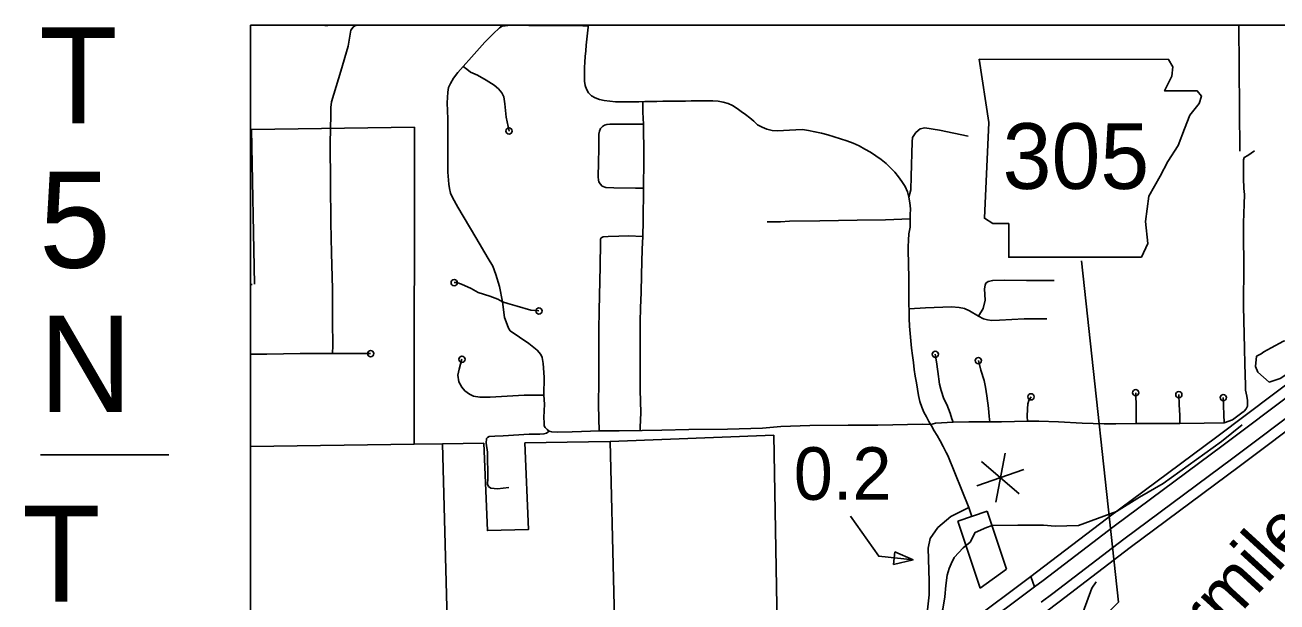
# Model space of a CAD drawing. Extents: x 1367863 to 1368197, y 380048 to 380261.
# Drawn here: x 1367952.41 to 1367991.45, y 380159.47 to 380177.46 of the extents above; entities that cross this region are included whole.
import ezdxf

# ---------------------------------------------------------------- set-up
doc = ezdxf.new("R2010")
doc.units = 0
for name, color, linetype in [('Level 10', 7, 'Continuous'), ('Level 15', 7, 'Continuous'), ('Level 21', 7, 'Continuous'), ('Level 31', 7, 'Continuous'), ('Level 33', 7, 'Continuous'), ('Level 34', 7, 'Continuous'), ('Level 35', 7, 'Continuous'), ('Level 45', 7, 'Continuous'), ('Level 48', 7, 'Continuous'), ('Level 5', 7, 'Continuous'), ('Level 6', 7, 'Continuous'), ('R_Border', 7, 'Continuous'), ('R_Draft', 7, 'Continuous'), ('R_No Plot', 7, 'Continuous')]:
    doc.layers.add(name, color=color, linetype=linetype)

msp = doc.modelspace()

# ---------------------------------------------------------------- linework, layer by layer
at = {"layer": 'Level 10'}
msp.add_line((1367982.191, 380159.898), (1367983.016, 380160.493), dxfattribs=at)
for points in [[(1367982.415, 380162.299), (1367981.495, 380161.993)], [(1367983.016, 380160.493), (1367982.415, 380162.299)], [(1367981.495, 380161.993), (1367982.191, 380159.898)]]:
    msp.add_lwpolyline(points, dxfattribs=at)
at = {"layer": 'Level 15'}
for p, q in [((1367981.823, 380158.812), (1367983.775, 380160.267)), ((1367983.888, 380159.94), (1367981.956, 380158.5))]:
    msp.add_line(p, q, dxfattribs=at)
for points in [[(1367983.775, 380160.267), (1367983.952, 380160.4), (1367986.169, 380162.096), (1367989.568, 380164.62), (1367994.115, 380168.041), (1367995.437, 380169.06), (1367995.925, 380169.499), (1367996.299, 380169.836), (1367997.817, 380171.432), (1367998.192, 380171.917), (1367999.213, 380173.375), (1368001.597, 380177.46)], [(1368001.979, 380177.46), (1367999.491, 380173.197), (1367998.457, 380171.722), (1367998.068, 380171.217), (1367996.529, 380169.599), (1367996.145, 380169.254), (1367995.648, 380168.807), (1367994.315, 380167.778), (1367989.766, 380164.356), (1367986.367, 380161.832), (1367984.151, 380160.136), (1367983.888, 380159.94)], [(1367984.089, 380159.461), (1367984.455, 380159.734), (1367986.671, 380161.43), (1367990.068, 380163.952), (1367994.62, 380167.377), (1367995.971, 380168.419), (1367996.483, 380168.878), (1367996.881, 380169.237), (1367998.451, 380170.888), (1367998.864, 380171.423), (1367999.916, 380172.924), (1368002.563, 380177.46)], [(1368002.944, 380177.46), (1368002.871, 380177.333), (1368000.194, 380172.746), (1367999.13, 380171.227), (1367998.702, 380170.673), (1367997.112, 380169.001), (1367996.703, 380168.633), (1367996.182, 380168.165), (1367994.82, 380167.114), (1367990.266, 380163.688), (1367986.87, 380161.166), (1367984.654, 380159.47), (1367984.225, 380159.15)], [(1367983.775, 380160.267), (1367983.888, 380159.94)], [(1367983.888, 380159.94), (1367983.775, 380160.267)]]:
    msp.add_lwpolyline(points, dxfattribs=at)
at = {"layer": 'Level 21'}
msp.add_lwpolyline([(1367982.162, 380176.391), (1367982.457, 380174.421), (1367982.326, 380171.433), (1367982.589, 380171.269), (1367983.081, 380171.269), (1367983.081, 380170.219), (1367987.218, 380170.219), (1367987.415, 380170.645), (1367987.349, 380171.335), (1367987.447, 380172.123), (1367987.808, 380172.747), (1367988.038, 380173.206), (1367988.367, 380173.699), (1367988.564, 380174.224), (1367988.728, 380174.651), (1367989.023, 380175.012), (1367989.089, 380175.242), (1367988.958, 380175.406), (1367987.94, 380175.406), (1367988.17, 380175.865), (1367988.202, 380176.161), (1367988.066, 380176.388)], close=True, dxfattribs=at)
msp.add_lwpolyline([(1367985.353, 380170.106), (1367986.507, 380159.464), (1367984.684, 380157.641)], dxfattribs=at)
at = {"layer": 'Level 31'}
for points in [[(1367961.935, 380174.233), (1367961.921, 380173.766), (1367961.941, 380172.529), (1367961.947, 380171.302), (1367961.968, 380170.349), (1367961.994, 380169.231), (1367962.001, 380168.218), (1367962.014, 380167.467), (1367962.001, 380167.212)], [(1367963.188, 380167.212), (1367962.558, 380167.219), (1367962.001, 380167.212), (1367960.995, 380167.212), (1367959.949, 380167.199), (1367959.444, 380167.199)]]:
    msp.add_lwpolyline(points, dxfattribs=at)
msp.add_circle((1367963.188, 380167.212), 0.097, dxfattribs=at)
at = {"layer": 'Level 33'}
for points in [[(1367962.114, 380177.46), (1367961.854, 380177.449), (1367961.76, 380177.442)], [(1367962.787, 380177.46), (1367962.698, 380177.435), (1367962.645, 380177.395), (1367962.571, 380177.301), (1367962.484, 380176.804), (1367962.256, 380176.026), (1367961.968, 380175.06), (1367961.947, 380174.886), (1367961.947, 380174.638), (1367961.935, 380174.233)], [(1367962.698, 380177.435), (1367962.564, 380177.456), (1367962.499, 380177.46)], [(1367966.075, 380176.167), (1367966.33, 380176.462), (1367966.752, 380176.925), (1367967.007, 380177.187), (1367967.208, 380177.375), (1367967.289, 380177.428)], [(1367967.289, 380177.428), (1367967.203, 380177.46)], [(1367967.289, 380177.428), (1367967.561, 380177.46)], [(1367967.795, 380177.46), (1367968.12, 380177.442), (1367968.925, 380177.448), (1367969.803, 380177.435), (1367969.973, 380177.439)], [(1367980.111, 380166.932), (1367980.082, 380167.153), (1367980.055, 380167.38), (1367980.029, 380167.607), (1367980.005, 380167.837), (1367979.987, 380168.069), (1367979.98, 380168.303), (1367979.973, 380168.537), (1367979.972, 380168.769), (1367979.971, 380169.001), (1367979.967, 380169.229), (1367979.966, 380169.456), (1367979.965, 380169.68), (1367979.962, 380169.902), (1367979.957, 380170.119), (1367979.951, 380170.332), (1367979.948, 380170.542), (1367979.954, 380170.748), (1367979.972, 380170.952), (1367980.007, 380171.152), (1367980.005, 380171.353), (1367980.009, 380171.546), (1367980.016, 380171.73), (1367980, 380171.91), (1367979.971, 380172.087), (1367979.928, 380172.255), (1367979.849, 380172.42), (1367979.752, 380172.576), (1367979.647, 380172.728), (1367979.527, 380172.87), (1367979.394, 380173.004), (1367979.257, 380173.144), (1367979.104, 380173.268), (1367978.941, 380173.382), (1367978.772, 380173.491), (1367978.597, 380173.593), (1367978.416, 380173.689), (1367978.23, 380173.773), (1367978.037, 380173.847), (1367977.84, 380173.912), (1367977.641, 380173.973), (1367977.442, 380174.033), (1367977.242, 380174.086), (1367977.042, 380174.132), (1367976.842, 380174.169), (1367976.651, 380174.199), (1367976.445, 380174.188), (1367976.25, 380174.181), (1367976.061, 380174.169), (1367975.877, 380174.163), (1367975.704, 380174.176), (1367975.544, 380174.214), (1367975.393, 380174.273), (1367975.25, 380174.345), (1367975.134, 380174.46), (1367975.007, 380174.562), (1367974.878, 380174.666), (1367974.745, 380174.766), (1367974.612, 380174.862), (1367974.475, 380174.948), (1367974.33, 380175.015), (1367974.178, 380175.058), (1367974.021, 380175.084), (1367973.858, 380175.091), (1367973.695, 380175.097), (1367973.527, 380175.096), (1367973.356, 380175.093), (1367973.183, 380175.091), (1367973.008, 380175.09), (1367972.833, 380175.088), (1367972.656, 380175.085), (1367972.477, 380175.083), (1367972.296, 380175.081), (1367972.112, 380175.08), (1367971.927, 380175.078), (1367971.741, 380175.075), (1367971.554, 380175.069), (1367971.369, 380175.066), (1367971.184, 380175.062), (1367971.001, 380175.063), (1367970.818, 380175.07), (1367970.642, 380175.087), (1367970.472, 380175.109), (1367970.319, 380175.142), (1367970.187, 380175.189), (1367970.074, 380175.257), (1367969.982, 380175.348), (1367969.916, 380175.457), (1367969.877, 380175.577), (1367969.858, 380175.705), (1367969.851, 380175.841), (1367969.852, 380175.986), (1367969.858, 380176.14), (1367969.863, 380176.303), (1367969.881, 380176.474), (1367969.894, 380176.651), (1367969.909, 380176.833), (1367969.926, 380177.017), (1367969.945, 380177.204), (1367969.967, 380177.389)], [(1367969.967, 380177.389), (1367969.975, 380177.46)], [(1367966.853, 380170.181), (1367966.47, 380170.83), (1367965.907, 380171.782), (1367965.74, 380172.084), (1367965.679, 380172.219), (1367965.646, 380172.366), (1367965.626, 380172.5), (1367965.592, 380172.876), (1367965.599, 380173.547), (1367965.592, 380174.533), (1367965.579, 380175.033), (1367965.599, 380175.369), (1367965.612, 380175.516), (1367965.679, 380175.637), (1367965.773, 380175.798), (1367965.907, 380175.979), (1367966.075, 380176.167)], [(1367967.503, 380174.155), (1367967.416, 380174.591), (1367967.376, 380175.007), (1367967.342, 380175.221), (1367967.275, 380175.349), (1367967.175, 380175.469), (1367967.04, 380175.584), (1367966.792, 380175.745), (1367966.517, 380175.892), (1367966.303, 380175.986), (1367966.189, 380176.08), (1367966.075, 380176.167)], [(1367971.672, 380170.862), (1367971.681, 380171.357), (1367971.698, 380172.376), (1367971.704, 380173.25), (1367971.701, 380173.659), (1367971.698, 380174.112), (1367971.694, 380174.364), (1367971.674, 380174.745), (1367971.671, 380175.073)], [(1367971.694, 380174.364), (1367971.279, 380174.366), (1367970.648, 380174.373), (1367970.548, 380174.359), (1367970.477, 380174.339), (1367970.417, 380174.299), (1367970.35, 380174.235), (1367970.32, 380174.155), (1367970.303, 380174.057), (1367970.303, 380173.608), (1367970.296, 380173.168), (1367970.279, 380172.727), (1367970.289, 380172.62), (1367970.299, 380172.57), (1367970.34, 380172.506), (1367970.41, 380172.432), (1367970.524, 380172.392), (1367970.772, 380172.382), (1367971.446, 380172.372), (1367971.698, 380172.376)], [(1367980.006, 380171.411), (1367979.241, 380171.386), (1367978.361, 380171.378), (1367977.196, 380171.352), (1367976.248, 380171.344), (1367975.963, 380171.319), (1367975.553, 380171.319)], [(1367970.314, 380164.799), (1367970.297, 380165.605), (1367970.307, 380166.373), (1367970.3, 380167.313), (1367970.3, 380167.957), (1367970.314, 380168.561), (1367970.347, 380169.944), (1367970.357, 380170.678), (1367970.354, 380170.781), (1367970.378, 380170.821), (1367970.441, 380170.852), (1367970.596, 380170.862), (1367970.931, 380170.875), (1367971.226, 380170.885), (1367971.672, 380170.862)], [(1367971.672, 380170.862), (1367971.658, 380170.473), (1367971.635, 380169.668), (1367971.618, 380169.115), (1367971.598, 380168.642), (1367971.588, 380168.2), (1367971.588, 380167.453), (1367971.591, 380166.695), (1367971.594, 380166.087), (1367971.607, 380165.366), (1367971.59, 380164.923), (1367971.587, 380164.814)], [(1367968.588, 380165.922), (1367968.603, 380166.478), (1367968.569, 380166.907), (1367968.536, 380167.088), (1367968.496, 380167.182), (1367968.375, 380167.316), (1367968.12, 380167.524), (1367967.543, 380167.92), (1367967.483, 380168.007), (1367967.443, 380168.121), (1367967.362, 380168.343), (1367967.295, 380168.826), (1367967.201, 380169.302), (1367967.087, 380169.684), (1367966.994, 380169.939), (1367966.853, 380170.181)], [(1367982.137, 380168.383), (1367982.284, 380168.617), (1367982.343, 380168.882), (1367982.33, 380169.234), (1367982.343, 380169.351), (1367982.372, 380169.406), (1367982.439, 380169.46), (1367982.582, 380169.498), (1367982.959, 380169.502), (1367983.638, 380169.494), (1367984.319, 380169.494), (1367984.503, 380169.498)], [(1367967.295, 380168.826), (1367967.154, 380168.912), (1367966.9, 380169.006), (1367966.538, 380169.12), (1367966.323, 380169.241), (1367966.021, 380169.375), (1367965.874, 380169.429), (1367965.793, 380169.429)], [(1367968.435, 380168.543), (1367968.18, 380168.57), (1367967.758, 380168.691), (1367967.463, 380168.771), (1367967.295, 380168.826)], [(1367979.973, 380168.613), (1367980.486, 380168.643), (1367981.303, 380168.668), (1367981.538, 380168.647), (1367981.706, 380168.617), (1367981.857, 380168.55), (1367982.137, 380168.383)], [(1367984.271, 380168.295), (1367984.134, 380168.295), (1367983.564, 380168.295), (1367982.794, 380168.261), (1367982.556, 380168.249), (1367982.421, 380168.269), (1367982.3, 380168.299), (1367982.137, 380168.383)], [(1367980.792, 380167.192), (1367980.829, 380166.953), (1367980.876, 380166.655), (1367980.926, 380166.261), (1367980.976, 380166.06), (1367981.064, 380165.804), (1367981.148, 380165.624), (1367981.257, 380165.36), (1367981.311, 380165.184), (1367981.352, 380165.073)], [(1367966.035, 380167.038), (1367965.944, 380166.724), (1367965.911, 380166.542), (1367965.936, 380166.335), (1367966.027, 380166.162), (1367966.126, 380166.054), (1367966.267, 380165.947), (1367966.391, 380165.881), (1367966.589, 380165.856), (1367966.919, 380165.856), (1367967.448, 380165.881), (1367967.977, 380165.922), (1367968.233, 380165.922), (1367968.588, 380165.922)], [(1367981.928, 380162.132), (1367981.836, 380162.41), (1367981.183, 380164.034), (1367981.134, 380164.132), (1367981.112, 380164.169), (1367981.034, 380164.317), (1367980.948, 380164.495), (1367980.855, 380164.655), (1367980.762, 380164.81), (1367980.674, 380164.956), (1367980.594, 380165.096), (1367980.515, 380165.237), (1367980.437, 380165.388), (1367980.369, 380165.547), (1367980.313, 380165.721), (1367980.272, 380165.906), (1367980.24, 380166.102), (1367980.207, 380166.3), (1367980.17, 380166.505), (1367980.139, 380166.715), (1367980.111, 380166.932)], [(1367982.135, 380166.994), (1367982.217, 380166.697), (1367982.313, 380166.37), (1367982.363, 380166.169), (1367982.401, 380165.901), (1367982.451, 380165.507), (1367982.468, 380165.247), (1367982.488, 380165.082)], [(1367987.043, 380165.995), (1367987.06, 380165.521), (1367987.051, 380165.194), (1367987.051, 380165.03)], [(1367988.412, 380165.03), (1367988.412, 380165.288), (1367988.394, 380165.624), (1367988.386, 380165.934)], [(1367968.588, 380165.922), (1367968.605, 380165.641), (1367968.588, 380165.219), (1367968.594, 380165.058), (1367968.601, 380164.964), (1367968.627, 380164.91), (1367968.691, 380164.847), (1367968.753, 380164.79)], [(1367983.78, 380165.865), (1367983.713, 380165.754), (1367983.675, 380165.645), (1367983.671, 380165.486), (1367983.662, 380165.247), (1367983.668, 380165.107)], [(1367989.772, 380165.84), (1367989.798, 380165.056)], [(1367967.498, 380163.038), (1367967.142, 380162.996), (1367966.936, 380163.021), (1367966.862, 380163.071), (1367966.828, 380163.145), (1367966.837, 380163.311), (1367966.828, 380164.137), (1367966.787, 380164.418), (1367966.804, 380164.567), (1367966.828, 380164.592), (1367966.886, 380164.625), (1367967.06, 380164.641), (1367967.324, 380164.649), (1367968.126, 380164.699), (1367968.464, 380164.699), (1367968.588, 380164.707), (1367968.671, 380164.732), (1367968.753, 380164.79)], [(1367968.753, 380164.79), (1367968.835, 380164.77), (1367969.003, 380164.763), (1367969.476, 380164.773), (1367970.334, 380164.8), (1367970.941, 380164.806), (1367971.651, 380164.815)], [(1367980.649, 380165.001), (1367980.392, 380165.011), (1367979, 380164.978), (1367978.08, 380164.978), (1367976.885, 380164.967), (1367975.98, 380164.939), (1367975.401, 380164.89), (1367974.311, 380164.856), (1367973.105, 380164.848), (1367972.262, 380164.823), (1367971.651, 380164.815)], [(1367987.051, 380165.03), (1367986.423, 380165.021), (1367986.061, 380165.021), (1367985.372, 380165.047), (1367984.632, 380165.09), (1367984.021, 380165.107), (1367983.668, 380165.107), (1367982.858, 380165.082), (1367982.488, 380165.082), (1367981.834, 380165.082), (1367981.352, 380165.073), (1367980.8, 380165.039), (1367980.649, 380165.001)], [(1367988.412, 380165.03), (1367987.516, 380165.03), (1367987.051, 380165.03)], [(1367989.798, 380165.056), (1367989.178, 380165.047), (1367988.412, 380165.03)], [(1367975.923, 380155.194), (1367976.455, 380155.327), (1367976.888, 380155.605), (1367979.98, 380158.235), (1367980.29, 380158.668), (1367980.537, 380159.132), (1367980.599, 380159.688), (1367980.599, 380160.121), (1367980.568, 380161.142), (1367980.63, 380161.452), (1367980.877, 380161.792), (1367981.279, 380162.132), (1367981.836, 380162.41)]]:
    msp.add_lwpolyline(points, dxfattribs=at)
for centre in [(1367967.503, 380174.155), (1367965.793, 380169.429), (1367968.435, 380168.543), (1367966.035, 380167.038), (1367980.792, 380167.192), (1367982.135, 380166.994), (1367983.78, 380165.865), (1367987.043, 380165.995), (1367988.386, 380165.934), (1367989.772, 380165.84)]:
    msp.add_circle(centre, 0.097, dxfattribs=at)
at = {"layer": 'Level 34'}
for points in [[(1367981.817, 380173.995), (1367980.923, 380174.182), (1367980.464, 380174.253), (1367980.321, 380174.223), (1367980.188, 380174.11), (1367980.086, 380173.957), (1367980.076, 380173.814), (1367980.045, 380172.732), (1367980.035, 380172.323), (1367979.971, 380172.087)], [(1367989.798, 380165.056), (1367990.061, 380165.146), (1367990.354, 380165.371)]]:
    msp.add_lwpolyline(points, dxfattribs=at)
at = {"layer": 'Level 35'}
msp.add_lwpolyline([(1367990.803, 380167.13), (1367990.774, 380166.811), (1367990.847, 380166.637), (1367991.202, 380166.325), (1367991.55, 380166.441), (1367991.717, 380166.55), (1367991.92, 380166.767), (1367991.862, 380167.261), (1367991.862, 380167.391), (1367991.877, 380167.493), (1367991.869, 380167.515), (1367991.739, 380167.609), (1367991.652, 380167.602), (1367991.26, 380167.398), (1367991.035, 380167.268), (1367990.948, 380167.203), (1367990.803, 380167.13)], dxfattribs=at)
at = {"layer": 'Level 45'}
msp.add_lwpolyline([(1367990.354, 380165.371), (1367990.422, 380165.423), (1367990.489, 380165.49), (1367990.522, 380165.574), (1367990.522, 380165.658), (1367990.522, 380165.75), (1367990.506, 380165.884), (1367990.464, 380166.068), (1367990.464, 380166.219), (1367990.447, 380166.899), (1367990.43, 380167.376), (1367990.405, 380168.693), (1367990.413, 380170.001), (1367990.405, 380170.869), (1367990.405, 380171.288), (1367990.422, 380171.875), (1367990.43, 380172.177), (1367990.413, 380172.361), (1367990.397, 380172.68), (1367990.397, 380173.259), (1367990.422, 380173.326), (1367990.539, 380173.393), (1367990.74, 380173.535)], dxfattribs=at)
at = {"layer": 'Level 48'}
for p, q in [((1367982.967, 380164.105), (1367982.679, 380162.58)), ((1367983.555, 380163.599), (1367982.09, 380163.086)), ((1367982.234, 380163.849), (1367983.411, 380162.837))]:
    msp.add_line(p, q, dxfattribs=at)
msp.add_lwpolyline([(1367980.102, 380160.781), (1367979.03, 380160.895), (1367978.145, 380162.141)], dxfattribs=at)
msp.add_lwpolyline([(1367979.53, 380161.035), (1367979.492, 380160.641), (1367980.102, 380160.781)], close=True, dxfattribs=at)
at = {"layer": 'Level 5'}
msp.add_lwpolyline([(1367970.655, 380164.472), (1367971.116, 380145.679)], dxfattribs=at)
at = {"layer": 'Level 6'}
for points in [[(1367990.26, 380177.46), (1367990.29, 380173.528)], [(1367959.474, 380174.198), (1367964.553, 380174.27)], [(1367959.474, 380174.198), (1367959.57, 380169.374)], [(1367964.553, 380174.27), (1367964.544, 380164.385)], [(1367959.494, 380169.372), (1367959.444, 380169.372)], [(1367990.357, 380164.996), (1367989.72, 380164.476), (1367987.902, 380163.167), (1367987.159, 380162.739), (1367986.44, 380162.286), (1367985.261, 380161.85), (1367984.533, 380161.833), (1367984.17, 380161.866), (1367983.362, 380161.866), (1367982.571, 380161.857)], [(1367964.544, 380164.385), (1367959.444, 380164.313)], [(1367965.424, 380164.398), (1367964.544, 380164.385)], [(1367965.424, 380164.398), (1367964.544, 380164.385)], [(1367966.717, 380164.416), (1367965.424, 380164.398)], [(1367965.424, 380164.398), (1367965.677, 380154.995)], [(1367967.998, 380164.434), (1367968.111, 380161.729), (1367966.83, 380161.696), (1367966.717, 380164.416)], [(1367975.756, 380164.667), (1367970.655, 380164.472), (1367969.977, 380164.463), (1367967.998, 380164.434)], [(1367975.923, 380155.206), (1367975.756, 380164.667)], [(1367977.254, 380155.244), (1367977.828, 380155.633), (1367978.636, 380156.306), (1367979.58, 380157.144), (1367980.318, 380157.876), (1367980.524, 380158.147), (1367980.796, 380158.667), (1367981.026, 380159.245), (1367981.091, 380159.629), (1367981.12, 380159.977), (1367981.161, 380160.302), (1367981.226, 380160.508), (1367981.285, 380160.656), (1367981.386, 380160.85), (1367981.663, 380161.157), (1367981.881, 380161.334), (1367982.035, 380161.63), (1367982.389, 380161.795), (1367982.571, 380161.857)], [(1367984.537, 380156.429), (1367984.639, 380156.599), (1367984.97, 380156.931), (1367985.26, 380157.869), (1367985.287, 380158.848), (1367985.674, 380159.897), (1367985.809, 380160.1)]]:
    msp.add_lwpolyline(points, dxfattribs=at)
at = {"layer": 'R_Border'}
msp.add_line((1367956.894, 380164.061), (1367952.895, 380164.061), dxfattribs=at)
at = {"layer": 'R_No Plot'}
msp.add_lwpolyline([(1367959.444, 380177.46), (1368103.344, 380177.46), (1368103.344, 380096.865), (1367959.444, 380096.865)], close=True, dxfattribs=at)

# ---------------------------------------------------------------- texts
at = {"layer": 'Level 21'}
msp.add_text('305', height=2.0492, dxfattribs=at).set_placement((1367982.89, 380172.349))
at = {"layer": 'Level 35'}
msp.add_text('Fourmile', height=1.6394, rotation=47.5543, dxfattribs=at).set_placement((1367986.857, 380155.33))
at = {"layer": 'Level 48'}
msp.add_text('0.2', height=1.6394, dxfattribs=at).set_placement((1367976.381, 380162.654))
at = {"layer": 'R_Draft'}
for s, p in [('T', (1367952.852, 380174.392)), ('5', (1367952.852, 380169.892)), ('N', (1367952.852, 380165.392)), ('T', (1367952.323, 380159.476))]:
    msp.add_text(s, height=3, dxfattribs=at).set_placement(p)

doc.saveas('drawing.dxf')
